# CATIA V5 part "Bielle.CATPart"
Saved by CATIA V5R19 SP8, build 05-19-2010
Part number: Bielle
Revision: ANY
Definition: UNKNOWN
Nomenclature: 19
Source: Unknown
Bounding box of the stored display mesh (mm): x -44 to 2.5, y -6 to 2.5, z -4 to 13.5
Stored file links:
  D:\Documents\1_Travail\2- 2I2D\1 - Cours et TD\2- TD\3-TD Assemblage\Pompe AirMan\Bielle.CATPart
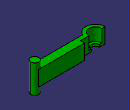
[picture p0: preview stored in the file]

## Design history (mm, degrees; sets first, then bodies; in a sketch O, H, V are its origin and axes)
Body1 "Extrusion2" (main body)
  Solid1: solid without history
